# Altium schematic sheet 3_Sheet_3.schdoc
size 830 x 271 mm; Name: A_Customize; Symbol: A_Customize; Device: A_Customize; @Project Name: MyOwnMP3_PCB; REV: 1.0; Date: 2026-02-28; Sheet: 1/1; Draw By: maxyusyuk; Company: Your Company; Convert to PCB: yes; Add into BOM: yes; spicePre: .; @Page No: 3; @Page Count: 3; @Schematic Name: MyOwnMP3; @Board Name: MyOwnMP3; @Update Date: 2026-04-22; @Create Time: 17:19:00; @Update Time: 22:09:50; @Page Name: Sheet_3; @Create Date: 2026-03-28
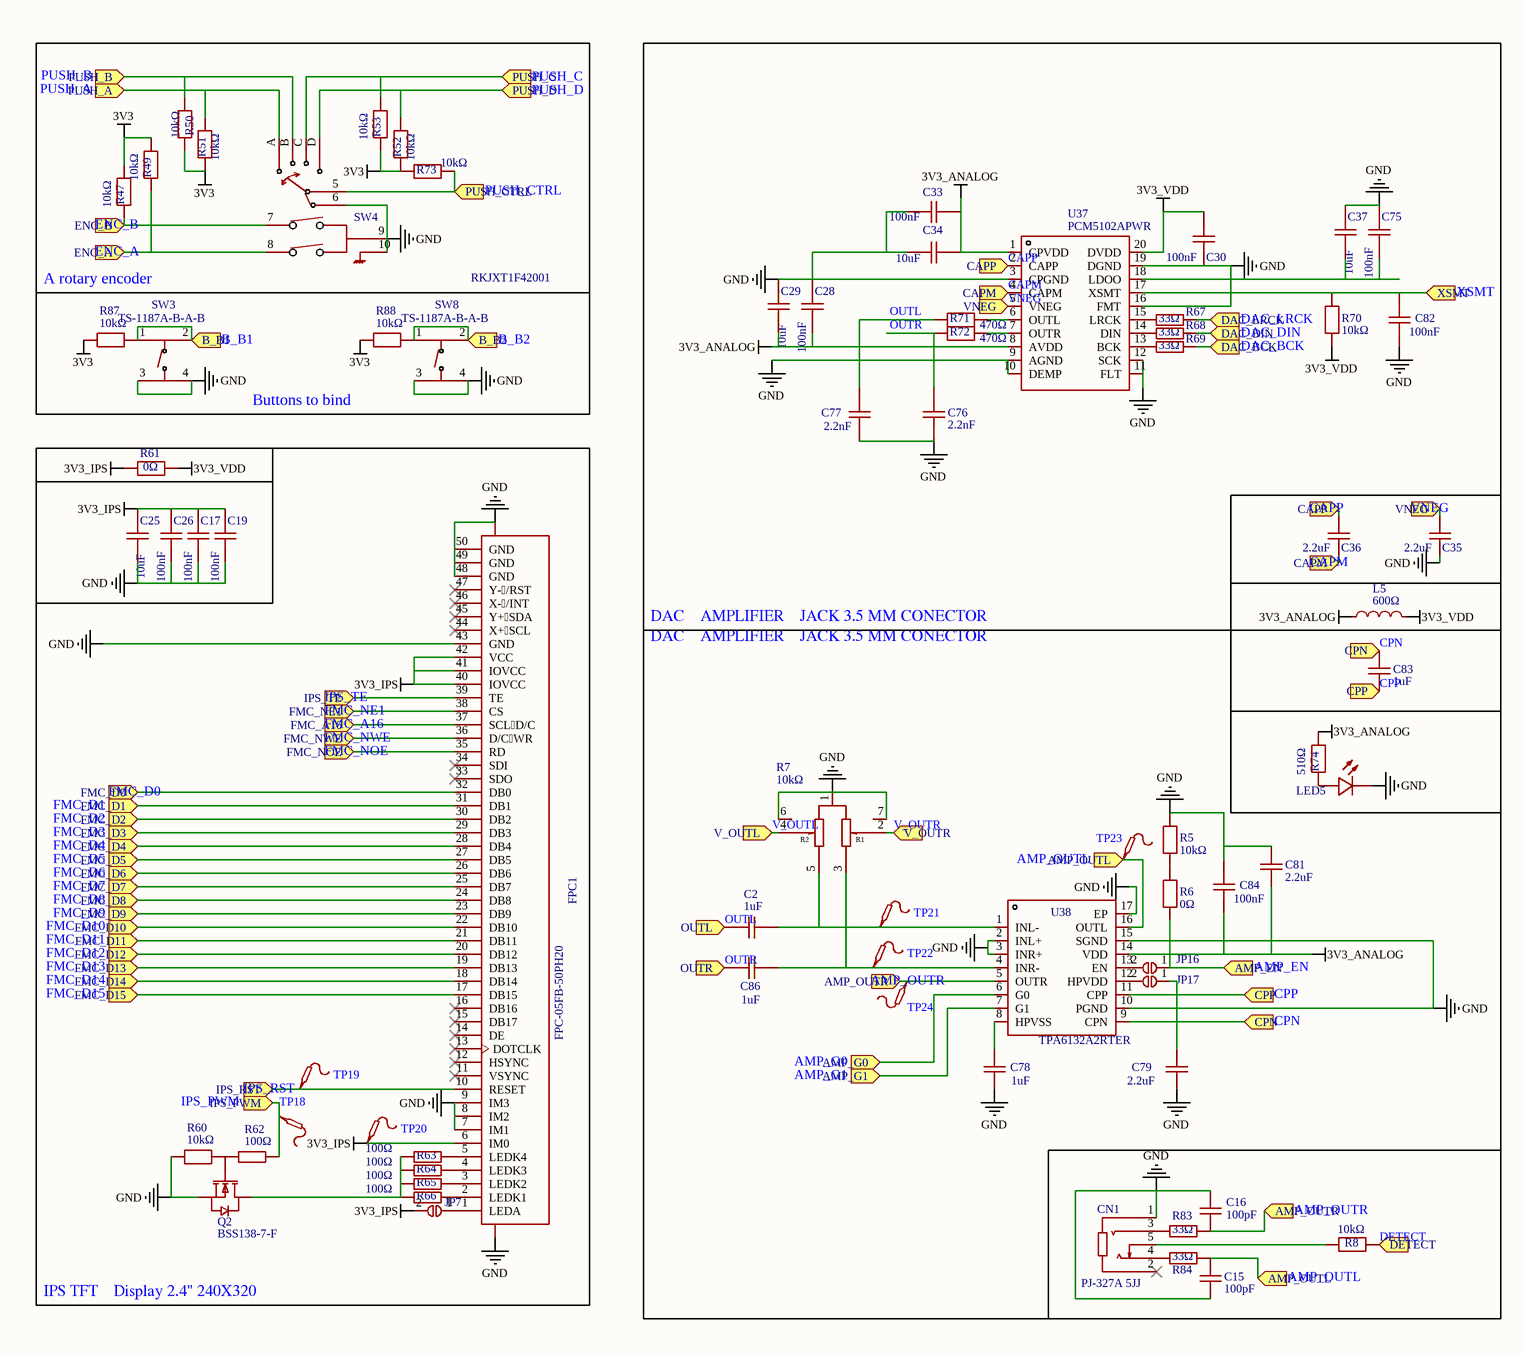
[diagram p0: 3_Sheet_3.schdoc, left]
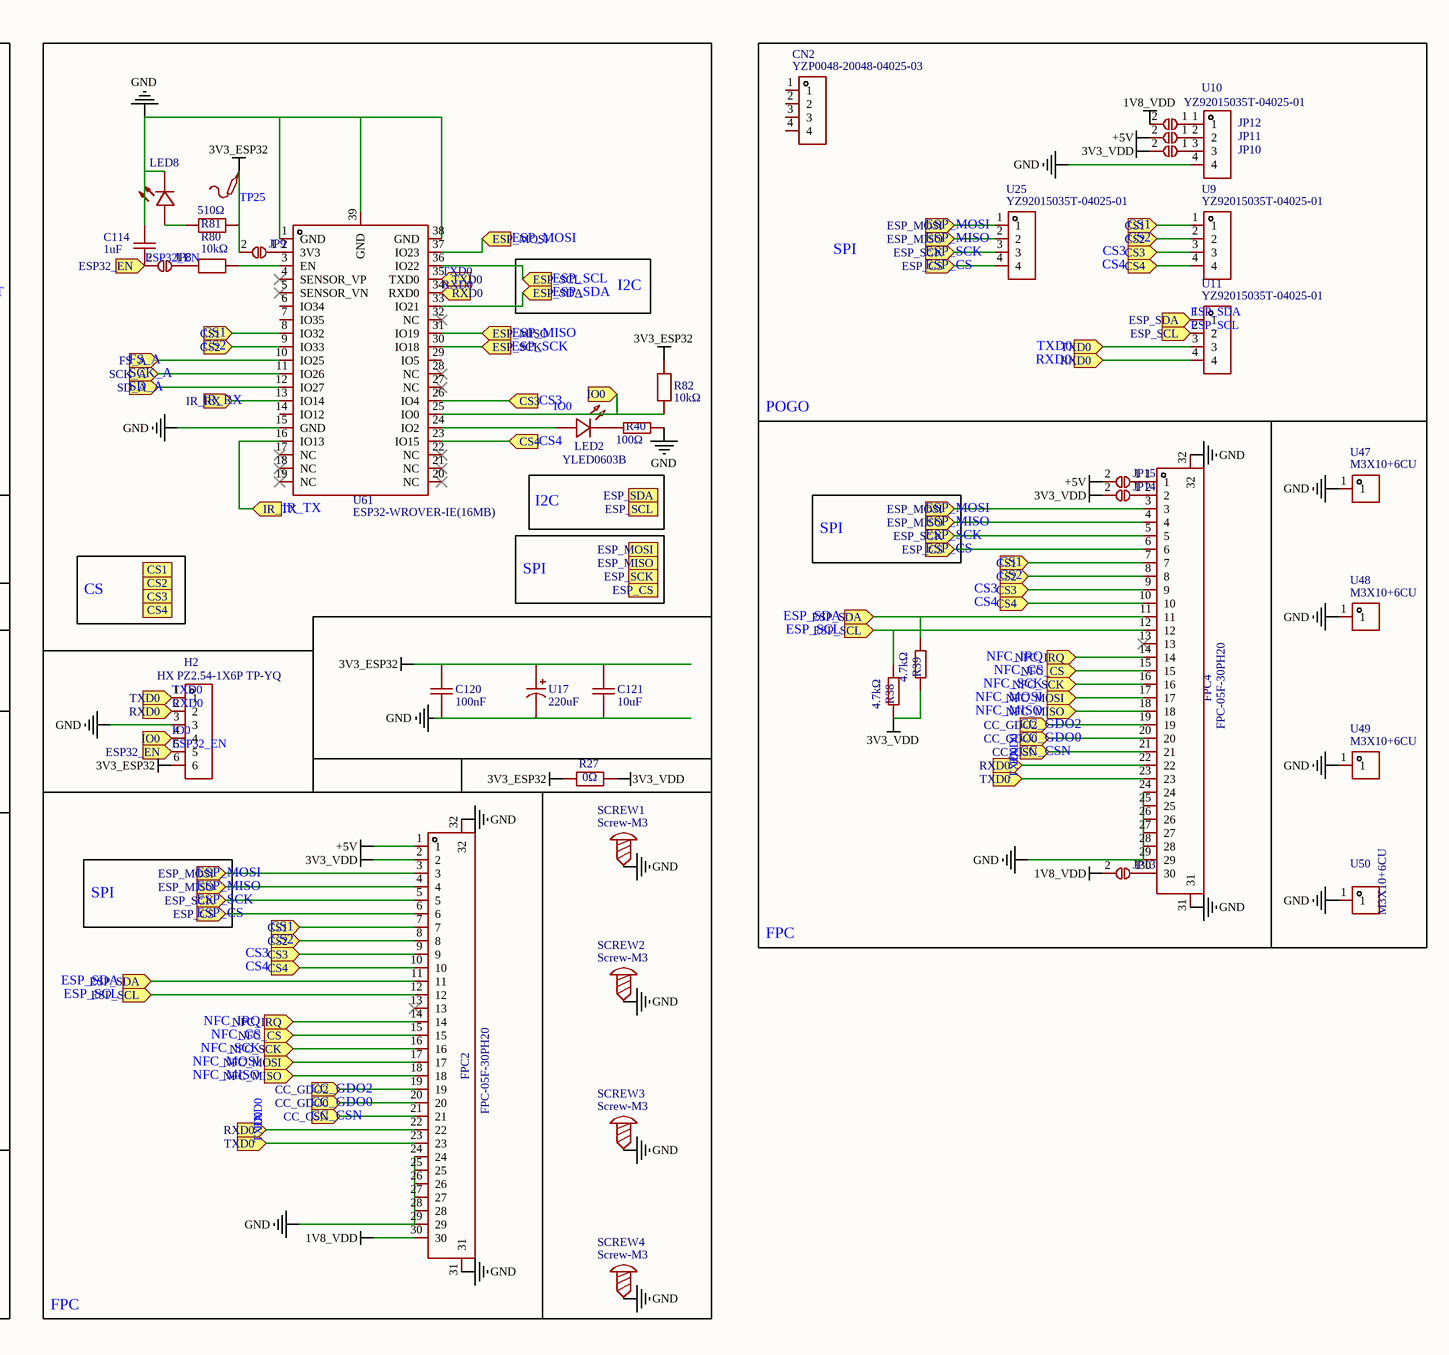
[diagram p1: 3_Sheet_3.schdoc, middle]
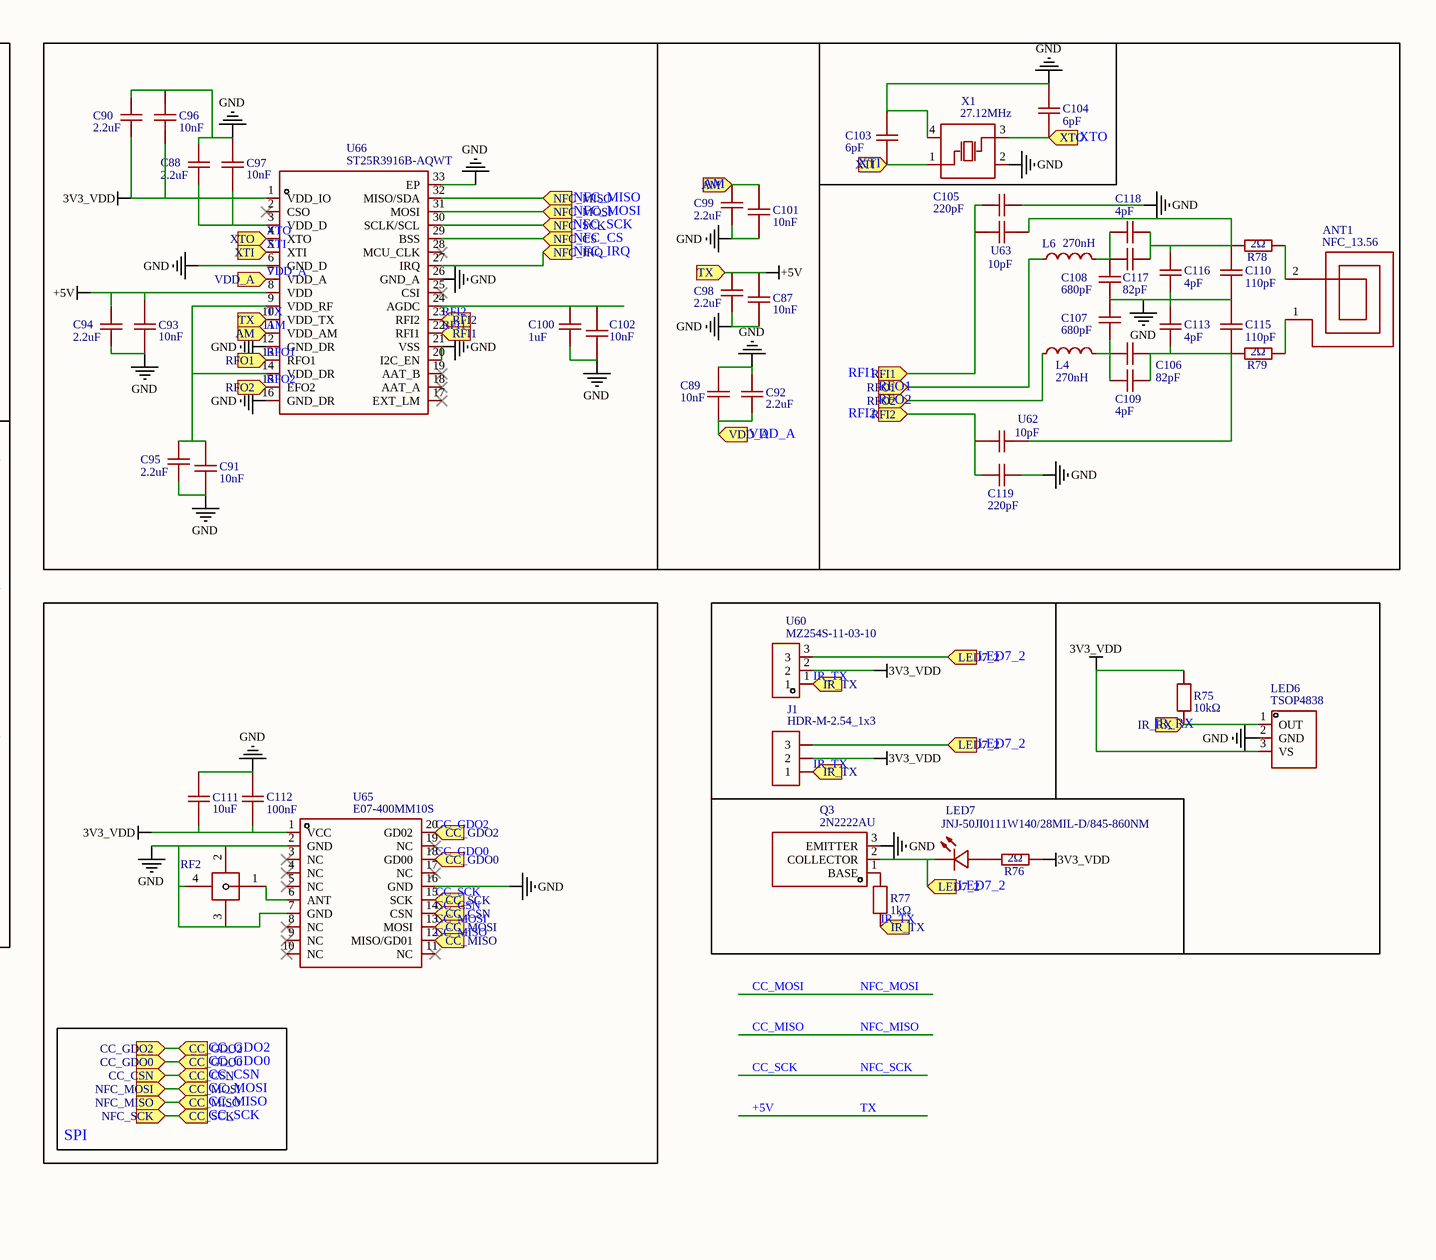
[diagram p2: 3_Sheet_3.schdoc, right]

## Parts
ANT1  NFC_13.56  [NFC ANTENNA]
C2  1uF  [C0603]
C15  100pF  [C0603]
C16  100pF  [C0603]
C17  100nF  [C0603]
C19  100nF  [C0603]
C25  10uF  [C1206]
C26  100nF  [C0603]
C28  100nF  [C0603]
C29  10uF  [C1206]
C30  100nF  [C0603]
C33  100nF  [C0603]
C34  10uF  [C1206]
C35  2.2uF  [C0603]
C36  2.2uF  [C0603]
C37  10uF  [C1206]
C75  100nF  [C0603]
C76  2.2nF  [C0805]
C77  2.2nF  [C0805]
C78  1uF  [C0603]
C79  2.2uF  [C0603]
C81  2.2uF  [C0603]
C82  100nF  [C0603]
C83  1uF  [C0603]
C84  100nF  [C0603]
C86  1uF  [C0603]
C87  10nF  [C0603]
C88  2.2uF  [C0603]
C89  10nF  [C0603]
C90  2.2uF  [C0603]
C91  10nF  [C0603]
C92  2.2uF  [C0603]
C93  10nF  [C0603]
C94  2.2uF  [C0603]
C95  2.2uF  [C0603]
C96  10nF  [C0603]
C97  10nF  [C0603]
C98  2.2uF  [C0603]
C99  2.2uF  [C0603]
C100  1uF  [C0603]
C101  10nF  [C0603]
C102  10nF  [C0603]
C103  6pF  [C0603]
C104  6pF  [C0603]
C105  220pF  [C0402]
C106  82pF  [C0603]
C107  680pF  [C0603]
C108  680pF  [C0603]
C109  4pF  [C0402]
C110  110pF  [C0402]
C111  10uF  [C1206]
C112  100nF  [C0603]
C113  4pF  [C0402]
C114  1uF  [C0603]
C115  110pF  [C0402]
C116  4pF  [C0402]
C117  82pF  [C0603]
C118  4pF  [C0402]
C119  220pF  [C0402]
C120  100nF  [C0603]
C121  10uF  [C1206]
CN1  PJ-327A 5JJ  [AUDIO-SMD_PJ-327A5JJ]
CN2  YZP0048-20048-04025-03
FPC1  FPC-05FB-50PH20  [FPC-SMD_50P-P0.50_FPC-05FB-50PH20]
FPC2  FPC-05F-30PH20  [FPC-SMD_30P-P0.50_XUNPU_FPC-05F-30PH20]
FPC4  FPC-05F-30PH20  [FPC-SMD_30P-P0.50_XUNPU_FPC-05F-30PH20]
H2  HX PZ2.54-1X6P TP-YQ  [HDR-SMD_6P-HX-PZ2.54-1X6P-TP-YQ]
J1  HDR-M-2.54_1x3  [HDR-M-2.54_1X3]
JP7  2P Solder UNBridge Jumper  [SOLDER BRIDGE 2P UNBRIDGED]  (value not drawn)
JP8  2P Solder UNBridge Jumper  [SOLDER BRIDGE 2P UNBRIDGED]  (value not drawn)
JP9  2P Solder UNBridge Jumper  [SOLDER BRIDGE 2P UNBRIDGED]  (value not drawn)
JP10  2P Solder UNBridge Jumper  [SOLDER BRIDGE 2P UNBRIDGED]  (value not drawn)
JP11  2P Solder UNBridge Jumper  [SOLDER BRIDGE 2P UNBRIDGED]  (value not drawn)
JP12  2P Solder UNBridge Jumper  [SOLDER BRIDGE 2P UNBRIDGED]  (value not drawn)
JP13  2P Solder UNBridge Jumper  [SOLDER BRIDGE 2P UNBRIDGED]  (value not drawn)
JP14  2P Solder UNBridge Jumper  [SOLDER BRIDGE 2P UNBRIDGED]  (value not drawn)
JP15  2P Solder UNBridge Jumper  [SOLDER BRIDGE 2P UNBRIDGED]  (value not drawn)
JP16  2P Solder UNBridge Jumper  [SOLDER BRIDGE 2P UNBRIDGED]  (value not drawn)
JP17  2P Solder UNBridge Jumper  [SOLDER BRIDGE 2P UNBRIDGED]  (value not drawn)
L4  270nH  [L0603]
L5  600Ω  [L0805]
L6  270nH  [L0603]
LED2  YLED0603B  [LED0603-FD]
LED5  YLED0603R  [LED0603-FD]  (value not drawn)
LED6  TSOP4838  [SENSOR-TH_TSOP4X]
LED7  JNJ-50JI0111W140/28MIL-D/845-860NM  [LED-SMD_L5.0-W5.0-LS5.3_C9900102386]
LED8  YLED0603R  [LED0603-FD]  (value not drawn)
Q2  BSS138-7-F  [SOT-23-3_L2.9-W1.6-P1.90-LS2.8-BR]
Q3  2N2222AU  [SOT-89-3_L4.5-W2.4-P1.50-LS4.0-BR]
R5  10kΩ  [R0603]
R6  0Ω  [R1206]
R7  10kΩ  [RES-SMD_RK10J12R0A0B]
R8  10kΩ  [R0603]
R27  0Ω  [R1206]
R38  4.7kΩ  [R0603]
R39  4.7kΩ  [R0603]
R40  100Ω  [R0603]
R47  10kΩ  [R0603]
R49  10kΩ  [R0603]
R50  10kΩ  [R0603]
R51  10kΩ  [R0603]
R52  10kΩ  [R0603]
R53  10kΩ  [R0603]
R60  10kΩ  [R0603]
R61  0Ω  [R1206]
R62  100Ω  [R0603]
R63  100Ω  [R0603]
R64  100Ω  [R0603]
R65  100Ω  [R0603]
R66  100Ω  [R0603]
R67  33Ω  [R0603]
R68  33Ω  [R0603]
R69  33Ω  [R0603]
R70  10kΩ  [R0603]
R71  470Ω  [R0603]
R72  470Ω  [R0603]
R73  10kΩ  [R0603]
R74  510Ω  [R0603]
R75  10kΩ  [R0603]
R76  2Ω  [R2512]
R77  1kΩ  [R2512]
R78  2Ω  [R2512]
R79  2Ω  [R2512]
R80  10kΩ  [R0603]
R81  510Ω  [R0603]
R82  10kΩ  [R0603]
R83  33Ω  [R0603]
R84  33Ω  [R0603]
R87  10kΩ  [R0603]
R88  10kΩ  [R0603]
RF2  HC-RF-IPEX0303-01  [IPEX-SMD_HC-RF-IPEX0303-01]  (value not drawn)
SCREW1  Screw-M3  [SCREW-M3]
SCREW2  Screw-M3  [SCREW-M3]
SCREW3  Screw-M3  [SCREW-M3]
SCREW4  Screw-M3  [SCREW-M3]
SW3  TS-1187A-B-A-B  [SW-SMD_4P-L5.1-W5.1-P3.70-LS6.5-TL_H1.5]
SW4  RKJXT1F42001  [SW-TH_RKJXT1F42001]
SW8  TS-1187A-B-A-B  [SW-SMD_4P-L5.1-W5.1-P3.70-LS6.5-TL_H1.5]
TP18  (no value)  [Test-Point-0.5mm]
TP19  (no value)  [Test-Point-0.5mm]
TP20  (no value)  [Test-Point-0.5mm]
TP21  (no value)  [Test-Point-0.5mm]
TP22  (no value)  [Test-Point-0.5mm]
TP23  (no value)  [Test-Point-0.5mm]
TP24  (no value)  [Test-Point-0.5mm]
TP25  (no value)  [Test-Point-0.5mm]
U9  YZ92015035T-04025-01  [CONN-SMD_4P-P2.50_YZ92015035T-04025-01]
U10  YZ92015035T-04025-01  [CONN-SMD_4P-P2.50_YZ92015035T-04025-01]
U11  YZ92015035T-04025-01  [CONN-SMD_4P-P2.50_YZ92015035T-04025-01]
U17  220uF  [CAP-SMD_BD6.3-L6.5-W6.5-LS7.2-FD]
U25  YZ92015035T-04025-01  [CONN-SMD_4P-P2.50_YZ92015035T-04025-01]
U37  PCM5102APWR  [TSSOP-20_L6.5-W4.4-P0.65-LS6.4-BL]
U38  TPA6132A2RTER  [WQFN-16_L3.0-W3.0-P0.50-TL-EP1.6]
U47  M3X10+6CU  [SMD_L4.7-W4.7-D3.0]
U48  M3X10+6CU  [SMD_L4.7-W4.7-D3.0]
U49  M3X10+6CU  [SMD_L4.7-W4.7-D3.0]
U50  M3X10+6CU  [SMD_L4.7-W4.7-D3.0]
U60  MZ254S-11-03-10  [HDR-SMD_3P-P2.54-H-M_MZ254S-11-03-10]
U61  ESP32-WROVER-IE(16MB)  [WIFI-SMD_ESP32-WROVER-E-N8R2]
U62  10pF  [C0603]
U63  10pF  [C0603]
U65  E07-400MM10S  [COMM-SMD_E07-400MM10S]
U66  ST25R3916B-AQWT  [VFQFPN-32_L5.0-W5.0-P0.50-TL-EP3.5]
X1  27.12MHz  [CRYSTAL-SMD_4P-L3.2-W2.5-BL]

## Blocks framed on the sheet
IPS TFT  Display 2.4" 240X320: C17 C19 C25 C26 FPC1 JP7 Q2 R60-R66 TP18-TP20
SPI: C111 C112 RF2 U65

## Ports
AM (in), AMP_EN (in), AMP_G0 (in), AMP_G1 (in), AMP_OUTL (in), AMP_OUTR (in), B_B1 (in), B_B2 (in), CAPM (in), CAPP (in), CC_CSN (in), CC_GDO0 (in), CC_GDO2 (in), CC_MISO (in), CC_MOSI (in), CC_SCK (in), CPN (in), CPP (in), CS1 (in), CS2 (in), CS3 (in), CS4 (in), DAC_BCK (in), DAC_DIN (in), DAC_LRCK (in), DETECT (in), ENC_A (in), ENC_B (in), ESP32_EN (in), ESP_CS (in), ESP_MISO (in), ESP_MOSI (in), ESP_SCK (in), ESP_SCL (in), ESP_SDA (in), FMC_A16 (in), FMC_D0 (in), FMC_D1 (in), FMC_D2 (in), FMC_D3 (in), FMC_D4 (in), FMC_D5 (in), FMC_D6 (in), FMC_D7 (in), FMC_D8 (in), FMC_D9 (in), FMC_D10 (in), FMC_D11 (in), FMC_D12 (in), FMC_D13 (in), FMC_D14 (in), FMC_D15 (in), FMC_NE1 (in), FMC_NOE (in), FMC_NWE (in), FS_A (in), IO0 (in), IPS_PWM (in), IPS_RST (in), IPS_TE (in), IR_RX (in), IR_TX (in), LED7_2 (in), NFC_CS (in), NFC_IRQ (in), NFC_MISO (in), NFC_MOSI (in), NFC_SCK (in), OUTL (in), OUTR (in), PUSH_A (in), PUSH_B (in), PUSH_C (in), PUSH_CTRL (in), PUSH_D (in), RFI1 (in), RFI2 (in), RFO1 (in), RFO2 (in), RXD0 (in), SCK_A (in), SD_A (in), TX (in), TXD0 (in), V_OUTL (in), V_OUTR (in), VDD_A (in), VNEG (in), XSMT (in), XTI (in), XTO (in)

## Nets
1V8_VDD: FPC2.30 JP12.2(B) JP13.2(B)
3V3: R47.2 R49.2 R50.2 R51.2 R52.1 R53.1 R73.2 R87.2 R88.2
3V3_ANALOG: C28.2 C29.1 C33.2 C34.1 C81.2 C84.2 L5.1 R74.1 U37.1(CPVDD) U37.8(AVDD) U38.14(VDD)
3V3_ESP32: C120.2 C121.1 H2.6 JP9.2(B) R27.1 R81.1 R82.1 TP25.1 U17.1
3V3_IPS: C17.1 C19.1 C25.2 C26.1 FPC1.6(IM0) FPC1.40(IOVCC) FPC1.41(IOVCC) FPC1.42(VCC) JP7.2(B) R61.1 TP20.1
3V3_VDD: C30.1 C90.1 C96.1 C111.2 C112.1 FPC2.2 J1.2 JP10.2(B) JP14.2(B) L5.2 LED6.3(VS) R27.2 R38.1 R39.1 R61.2 R70.2 R75.1 R76.2 U37.20(DVDD) U60.2 U65.1(VCC) U66.1(VDD_IO)
+5V: C87.2 C93.2 C94.2 C98.2 FPC2.1 JP11.2(B) JP15.2(B) U66.8(VDD) U66.10(VDD_TX) ; port TX  [also labelled TX]
GND: C15.1 C16.2 C17.2 C19.2 C25.1 C26.2 C28.1 C29.2 C30.2 C33.1 C34.2 C35.2 C37.2 C75.1 C76.1 C77.1 C78.1 C79.1 C81.1 C82.2 C84.1 C87.1 C88.2 C89.2 C90.2 C91.1 C92.1 C93.1 C94.1 C95.1 C96.2 C97.2 C98.1 C99.1 C100.2 C101.1 C102.1 C103.1 C104.1 C105.2 C107.2 C108.1 C110.1 C111.1 C112.2 C113.2 C114.1 C115.2 C116.1 C119.2 C120.1 C121.2 CN1.1 FPC1.7(IM1) FPC1.8(IM2) FPC1.9(IM3) FPC1.43(GND) FPC1.48(GND) FPC1.49(GND) FPC1.50(GND) FPC1.51(PAD1) FPC1.52(PAD2) FPC2.24 FPC2.25 FPC2.26 FPC2.27 FPC2.28 FPC2.29 FPC2.31 FPC2.32 FPC4.24 FPC4.25 FPC4.26 FPC4.27 FPC4.28 FPC4.29 FPC4.31 FPC4.32 H2.3 LED5.2(-) LED6.2(GND) LED8.2(-) Q2.2(S) Q3.3(EMITTER) R5.2 R7.1 R7.6(EH) R7.7(EH) R40.2 R60.2 RF2.2 RF2.3 RF2.4 SCREW1.1 SCREW2.1 SCREW3.1 SCREW4.1 SW3.3(C) SW3.4(D) SW4.6(COM) SW4.9(E_C) SW4.10 SW8.3(C) SW8.4(D) U10.4 U17.2 U37.3(CPGND) U37.9(AGND) U37.10(DEMP) U37.11(FLT) U37.12(SCK) U37.16(FMT) U37.19(DGND) U38.2(INL+) U38.3(INR+) U38.10(PGND) U38.15(SGND) U38.17(EP) U47.1 U48.1 U49.1 U50.1 U61.1(GND) U61.15(GND) U61.38(GND) U61.39(GND) U65.2(GND) U65.7(GND) U65.16(GND) U66.6(GND_D) U66.12(GND_DR) U66.16(GND_DR) U66.20(I2C_EN) U66.21(VSS) U66.26(GND_A) U66.33(EP) X1.2(GND) X1.4(GND)
AM: C99.2 C101.2 U66.11(VDD_AM) ; port AM
AMP_EN: JP16.1(A) R6.2 ; port AMP_EN
AMP_G0: U38.6(G0) ; port AMP_G0
AMP_G1: U38.7(G1) ; port AMP_G1
AMP_OUTL: C15.2 R84.2 TP23.1 U38.16(OUTL) ; port AMP_OUTL
AMP_OUTR: C16.1 R83.2 TP24.1 U38.5(OUTR) ; port AMP_OUTR
B_B1: R87.1 SW3.1(A) SW3.2(B) ; port B_B1
B_B2: R88.1 SW8.1(A) SW8.2(B) ; port B_B2
CAPM: C36.2 U37.4(CAPM) ; port CAPM
CAPP: C36.1 U37.2(CAPP) ; port CAPP
CC_CSN: FPC2.21 FPC4.21 U65.14(CSN) ; port CC_CSN
CC_GDO0: FPC2.20 FPC4.20 U65.18(GD00) ; port CC_GDO0
CC_GDO2: FPC2.19 FPC4.19 U65.20(GD02) ; port CC_GDO2
CC_MISO: FPC2.18 FPC4.18 U65.12(MISO/GD01) U66.32(MISO/SDA) ; port CC_MISO, port NFC_MISO  [also labelled NFC_MISO]
CC_MOSI: FPC2.17 FPC4.17 U65.13(MOSI) U66.31(MOSI) ; port CC_MOSI, port NFC_MOSI  [also labelled NFC_MOSI]
CC_SCK: FPC2.16 FPC4.16 U65.15(SCK) U66.30(SCLK/SCL) ; port CC_SCK, port NFC_SCK  [also labelled NFC_SCK]
CPN: C83.1 U38.9(CPN) ; port CPN
CPP: C83.2 U38.11(CPP) ; port CPP
CS1: FPC2.7 FPC4.7 U9.1 U61.8(IO32) ; port CS1
CS2: FPC2.8 FPC4.8 U9.2 U61.9(IO33) ; port CS2
CS3: FPC2.9 FPC4.9 U9.3 U61.26(IO4) ; port CS3
CS4: FPC2.10 FPC4.10 U9.4 U61.23(IO15) ; port CS4
DAC_BCK: R69.2 ; port DAC_BCK
DAC_DIN: R68.2 ; port DAC_DIN
DAC_LRCK: R67.2 ; port DAC_LRCK
DETECT: R8.1 ; port DETECT
ENC_A: R49.1 SW4.8(E_A) ; port ENC_A
ENC_B: R47.1 SW4.7(E_B) ; port ENC_B
ESP32_EN: C114.2 H2.5 JP8.2(B) ; port ESP32_EN
ESP_CS: FPC2.6 FPC4.6 U25.4 ; port ESP_CS
ESP_MISO: FPC2.4 FPC4.4 U25.2 U61.31(IO19) ; port ESP_MISO
ESP_MOSI: FPC2.3 FPC4.3 U25.1 U61.37(IO23) ; port ESP_MOSI
ESP_SCK: FPC2.5 FPC4.5 U25.3 U61.30(IO18) ; port ESP_SCK
ESP_SCL: FPC2.12 FPC4.12 R38.2 U11.2 U61.36(IO22) ; port ESP_SCL
ESP_SDA: FPC2.11 FPC4.11 R39.2 U11.1 U61.33(IO21) ; port ESP_SDA
FMC_A16: FPC1.37(SCL D/C) ; port FMC_A16
FMC_D0: FPC1.32(DB0) ; port FMC_D0
FMC_D1: FPC1.31(DB1) ; port FMC_D1
FMC_D2: FPC1.30(DB2) ; port FMC_D2
FMC_D3: FPC1.29(DB3) ; port FMC_D3
FMC_D4: FPC1.28(DB4) ; port FMC_D4
FMC_D5: FPC1.27(DB5) ; port FMC_D5
FMC_D6: FPC1.26(DB6) ; port FMC_D6
FMC_D7: FPC1.25(DB7) ; port FMC_D7
FMC_D8: FPC1.24(DB8) ; port FMC_D8
FMC_D9: FPC1.23(DB9) ; port FMC_D9
FMC_D10: FPC1.22(DB10) ; port FMC_D10
FMC_D11: FPC1.21(DB11) ; port FMC_D11
FMC_D12: FPC1.20(DB12) ; port FMC_D12
FMC_D13: FPC1.19(DB13) ; port FMC_D13
FMC_D14: FPC1.18(DB14) ; port FMC_D14
FMC_D15: FPC1.17(DB15) ; port FMC_D15
FMC_NE1: FPC1.38(CS) ; port FMC_NE1
FMC_NOE: FPC1.35(RD) ; port FMC_NOE
FMC_NWE: FPC1.36(D/C WR) ; port FMC_NWE
FS_A: U61.10(IO25) ; port FS_A
IO0: H2.4 R82.2 U61.25(IO0) ; port IO0
IPS_PWM: R62.2 TP18.1 ; port IPS_PWM
IPS_RST: FPC1.10(RESET) TP19.1 ; port IPS_RST
IPS_TE: FPC1.39(TE) ; port IPS_TE
IR_RX: LED6.1(OUT) R75.2 U61.13(IO14) ; port IR_RX
IR_TX: J1.1 R77.1 U60.1 U61.16(IO13) ; port IR_TX
LED7_2: J1.3 LED7.2(K) Q3.2(COLLECTOR) U60.3 ; port LED7_2
NFC_CS: FPC2.15 FPC4.15 U66.29(BSS) ; port NFC_CS
NFC_IRQ: FPC2.14 FPC4.14 U66.27(IRQ) ; port NFC_IRQ
OUTL: C2.2 ; port OUTL
OUTR: C86.2 ; port OUTR
PUSH_A: R51.1 SW4.A ; port PUSH_A
PUSH_B: R50.1 SW4.B ; port PUSH_B
PUSH_C: R53.2 SW4.C ; port PUSH_C
PUSH_CTRL: R73.1 SW4.5(PUSH) ; port PUSH_CTRL
PUSH_D: R52.2 SW4.D ; port PUSH_D
RFI1: C105.1 U63.1 U66.22(RFI1) ; port RFI1
RFI2: C119.1 U62.1 U66.23(RFI2) ; port RFI2
RFO1: L6.1 U66.13(RFO1) ; port RFO1
RFO2: L4.1 U66.15(EFO2) ; port RFO2
RXD0: FPC2.22 FPC4.22 H2.2 U11.4 U61.34(RXD0) ; port RXD0
SCK_A: U61.11(IO26) ; port SCK_A
SD_A: U61.12(IO27) ; port SD_A
TXD0: FPC2.23 FPC4.23 H2.1 U11.3 U61.35(TXD0) ; port TXD0
V_OUTL: R7.4 ; port V_OUTL
V_OUTR: R7.2 ; port V_OUTR
VDD_A: C89.1 C92.2 U66.7(VDD_A) ; port VDD_A
VNEG: C35.1 U37.5(VNEG) ; port VNEG
XSMT: C82.1 R70.1 U37.17(XSMT) ; port XSMT
XTI: C103.2 U66.5(XTI) X1.1(OSC1) ; port XTI
XTO: C104.2 U66.4(XTO) X1.3(OSC2) ; port XTO
NetANT1_1: ANT1.1 R79.2
NetANT1_2: ANT1.2 R78.2
NetC2_1: C2.1 R7.5 TP21.1 U38.1(INL-)
NetC37_1: C37.1 C75.2 U37.18(LDOO)
NetC76_2: C76.2 R72.1
NetC77_2: C77.2 R71.1
NetC78_2: C78.2 U38.8(HPVSS)
NetC79_2: C79.2 JP17.1(A)
NetC86_1: C86.1 R7.3 TP22.1 U38.4(INR-)
NetC88_1: C88.1 C97.1 U66.3(VDD_D)
NetC91_2: C91.2 C95.2 U66.9(VDD_RF) U66.14(VDD_DR)
NetC100_1: C100.1 C102.2 U66.24(AGDC)
NetC106_1: C106.1 C107.1 C109.2 L4.2
NetC106_2: C106.2 C109.1 C113.1 C115.1 R79.1 U62.2
NetC108_2: C108.2 C117.1 C118.2 L6.2
NetC110_2: C110.2 C116.2 C117.2 C118.1 R78.1 U63.2
NetCN1_3: CN1.3 R83.1
NetCN1_4: CN1.4 R84.1
NetCN1_5: CN1.5 R8.2
NetFPC1_1: FPC1.1(LEDA) JP7.1(A)
NetFPC1_2: FPC1.2(LEDK1) R66.2
NetFPC1_3: FPC1.3(LEDK2) R65.2
NetFPC1_4: FPC1.4(LEDK3) R64.2
NetFPC1_5: FPC1.5(LEDK4) R63.2
NetFPC4_1: FPC4.1 JP15.1(A)
NetFPC4_2: FPC4.2 JP14.1(A)
NetFPC4_30: FPC4.30 JP13.1(A)
NetJP8_1: JP8.1(A) R80.1
NetJP9_1: JP9.1(A) U61.2(3V3)
NetJP10_1: JP10.1(A) U10.3
NetJP11_1: JP11.1(A) U10.2
NetJP12_1: JP12.1(A) U10.1
NetJP16_2: JP16.2(B) U38.13(EN)
NetJP17_2: JP17.2(B) U38.12(HPVDD)
NetLED2_1: LED2.1(A) U61.24(IO2)
NetLED2_2: LED2.2(K) R40.1
NetLED5_1: LED5.1(+) R74.2
NetLED7_1: LED7.1(A) R76.1
NetLED8_1: LED8.1(+) R81.2
NetQ2_1: Q2.1(G) R60.1 R62.1
NetQ2_3: Q2.3(D) R63.1 R64.1 R65.1 R66.1
NetQ3_1: Q3.1(BASE) R77.2
NetR5_1: R5.1 R6.1
NetR67_1: R67.1 U37.15(LRCK)
NetR68_1: R68.1 U37.14(DIN)
NetR69_1: R69.1 U37.13(BCK)
NetR71_2: R71.2 U37.6(OUTL)
NetR72_2: R72.2 U37.7(OUTR)
NetR80_2: R80.2 U61.3(EN)
NetRF2_1: RF2.1 U65.6(ANT)

Not connected (* = marked no-connect by the designer): CN1 2*; CN2 1 2 3 4; FPC1 11(VSYNC)* 12(HSYNC)* 13(DOTCLK)* 14(DE)* 15(DB17)* 16(DB16)* 33(SDO)* 34(SDI)* 44(X+ SCL)* 45(Y+ SDA)* 46(X- /INT)* 47(Y- /RST)*; FPC2 13*; FPC4 13*; U61 4(SENSOR_VP)* 5(SENSOR_VN)* 6(IO34) 7(IO35) 14(IO12) 17(NC)* 18(NC)* 19(NC)* 20(NC)* 21(NC)* 22(NC)* 27(NC)* 28(NC)* 29(IO5) 32(NC)*; U65 3(NC)* 4(NC)* 5(NC)* 8(NC)* 9(NC)* 10(NC)* 11(NC)* 17(NC)* 19(NC)*; U66 2(CSO)* 17(EXT_LM)* 18(AAT_A)* 19(AAT_B)* 25(CSI)* 28(MCU_CLK)*

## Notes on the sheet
- A rotary encoder
- I2C
- SPI
- Buttons to bind
- POGO
- DAC  AMPLIFIER  JACK 3.5 MM CONECTOR
- CS
- FPC
- Labels drawn without touching a wire or pin: AM, AMP_EN, AMP_G0, AMP_G1, AMP_OUTL, AMP_OUTR, B_B1, B_B2, CAPM, CAPP, CC_CSN, CC_GDO0, CC_GDO2, CC_MISO, CC_MOSI, CC_SCK, CPN, CPP, CS1, CS2, CS3, CS4, DAC_BCK, DAC_DIN, DAC_LRCK, ENC_A, ENC_B, ESP_CS, ESP_MISO, ESP_MOSI, ESP_SCK, ESP_SCL, ESP_SDA, FMC_A16, FMC_D0, FMC_D1, FMC_D2, FMC_D3, FMC_D4, FMC_D5, FMC_D6, FMC_D7, FMC_D8, FMC_D9, FMC_D10, FMC_D11, FMC_D12, FMC_D13, FMC_D14, FMC_D15, FMC_NE1, FMC_NOE, FMC_NWE, FS_A, IPS_PWM, IPS_RST, IPS_TE, IR_RX, IR_TX, LED7_2, NFC_CS, NFC_IRQ, NFC_MISO, NFC_MOSI, NFC_SCK, OUTL, OUTR, PUSH_A, PUSH_B, PUSH_C, PUSH_CTRL, PUSH_D, RFI1, RFI2, RFO1, RFO2, RXD0, SCK_A, SD_A, TXD0, VDD_A, VNEG, XSMT, XTI, XTO

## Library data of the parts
ANT1 = NFC_13.56: Convert to PCB: yes; Add into BOM: no; Contributor: diegozalez
C2 C86 = 1uF: Manufacturer: SAMSUNG(三星); Manufacturer Part: CL10B105KB8NQNC; Convert to PCB: yes; Contributor: lcsc; nameAlias: Value
C15 C16 = 100pF: Manufacturer Part: CL10C101JB8NNNC; Manufacturer: SAMSUNG(三星); Convert to PCB: yes; nameAlias: Value
C17 C19 C26 C28 C30 C33 C75 C82 C84 C112 C120 = 100nF: Manufacturer: YAGEO(国巨); Manufacturer Part: CC0603JRX7R8BB104; Convert to PCB: yes; nameAlias: Value; Contributor: LCSC
C25 C29 C34 C37 C111 C121 = 10uF: Manufacturer: CCTC(三环); Manufacturer Part: TCC1206X7R106K160HT; Convert to PCB: yes; nameAlias: Value; Contributor: LCSC
C35 C36 C79 C81 C88 C90 C92 C94 C95 C98 C99 = 2.2uF: Manufacturer: YAGEO(国巨); Manufacturer Part: CC0603KRX5R7BB225; Convert to PCB: yes; nameAlias: Value
C76 C77 = 2.2nF: Manufacturer: Walsin(华新科); Manufacturer Part: 0805B222K102CT; Convert to PCB: yes; nameAlias: Value; Contributor: lcsc
C78 C83 C100 C114 = 1uF: Manufacturer Part: CC0603KRX5R8BB105; Manufacturer: YAGEO(国巨); Convert to PCB: yes; nameAlias: Value
C87 C89 C91 C93 C96 C97 C101 C102 = 10nF: Manufacturer: TORCH(火炬); Manufacturer Part: CC0603X7R25V103KN; Convert to PCB: yes; Contributor: lcsc; nameAlias: Value
C103 C104 = 6pF: Manufacturer: YAGEO(国巨); Manufacturer Part: CC0603CRNPO9BN6R0; Convert to PCB: yes; nameAlias: Value; Contributor: LCSC
C105 C119 = 220pF: Manufacturer: FH(风华); Manufacturer Part: 0402CG221J500NT; Convert to PCB: yes; nameAlias: Value
C106 C117 = 82pF: Manufacturer: FH(风华); Manufacturer Part: 0603CG820J500NT; Convert to PCB: yes; nameAlias: Value
C107 C108 = 680pF: Manufacturer: FH(风华); Manufacturer Part: 0603B681K500NT; Convert to PCB: yes; nameAlias: Value
C109 C113 C116 C118 = 4pF: Manufacturer: FH(风华); Manufacturer Part: 0402CG4R0C500NT; Convert to PCB: yes; nameAlias: Value
C110 C115 = 110pF: Manufacturer: muRata(村田); Manufacturer Part: GRM1555C1H111JA01D; Convert to PCB: yes; nameAlias: Value; Contributor: lcsc
CN1 = PJ-327A 5JJ: Manufacturer: SHOU HAN(首韩); Convert to PCB: yes; Contributor: LCSC
CN2 = YZP0048-20048-04025-03: Manufacturer: Xinyangze(鑫扬泽); Convert to PCB: no; Origin Footprint: CONN-SMD_4P-P2.50-YZP0048-20048-04025-03; Contributor: lcsc
FPC1 = FPC-05FB-50PH20: Manufacturer: XUNPU(讯普); Symbol: BuyDisplay ER-TFT024IPS-3 FPC - 50pin 0.5mm; Add into BOM: yes; Locking Feature: Hinged Lid; Number of Contacts: 50P; Pitch: 0.5mm; FFC, FCB Thickness: 0.3mm; Rated Voltage (Max): 50V; Current Rating (Max): 500mA
FPC2 FPC4 = FPC-05F-30PH20: Manufacturer: XUNPU(讯普); Convert to PCB: yes; Contributor: LCSC
H2 = HX PZ2.54-1X6P TP-YQ: Manufacturer: hanxia(韩下); Convert to PCB: yes
J1 = HDR-M-2.54_1x3: Convert to PCB: yes; Add into BOM: no; Contributor: LCEDA_Lib
JP7-JP17 = 2P Solder UNBridge Jumper: Manufacturer Part: DNP; Convert to PCB: yes; Add into BOM: no; Contributor: RonNovy
L4 L6 = 270nH: Manufacturer: FH(风华); Manufacturer Part: VHF160808HR27JT; Convert to PCB: yes; Add into BOM: no; nameAlias: Value; Contributor: LCSC
L5 = 600Ω: Manufacturer: FH(风华); Manufacturer Part: CBG201209U601T; Convert to PCB: yes; nameAlias: Value
LED2 = YLED0603B: Manufacturer: YONGYUTAI(永裕泰); Convert to PCB: yes; Contributor: lcsc
LED5 LED8 = YLED0603R: Manufacturer: YONGYUTAI(永裕泰); Convert to PCB: yes; Contributor: lcsc
LED6 = TSOP4838: Manufacturer: VISHAY(威世); Convert to PCB: yes; Contributor: LCSC
LED7 = JNJ-50JI0111W140/28MIL-D/845-860NM: Manufacturer: JNJOPTO(强生光电); Convert to PCB: yes; Contributor: lcsc
Q2 = BSS138-7-F: Manufacturer: DIODES(美台); Convert to PCB: yes
Q3 = 2N2222AU: Manufacturer: CBI(创基); Convert to PCB: yes; Contributor: lcsc
R5 R8 R47 R49-R53 R60 R70 R73 R75 R80 R82 R87 R88 = 10kΩ: Manufacturer: VO(翔胜); Manufacturer Part: SCR0603J10K; Convert to PCB: yes; nameAlias: Value; Contributor: lcsc
R6 R27 R61 = 0Ω: Manufacturer: JIERR(捷而瑞); Manufacturer Part: JER1206F1R000; Convert to PCB: yes; nameAlias: Value; Contributor: lcsc
R7 = 10kΩ: Manufacturer: ALPSALPINE(阿尔卑斯阿尔派); Manufacturer Part: RK10J12R0A0B; Convert to PCB: yes; Contributor: LCSC; nameAlias: Value
R38 R39 = 4.7kΩ: Manufacturer: UNI-ROYAL(厚声); Manufacturer Part: 0603WAF4701T5E; Convert to PCB: yes; nameAlias: Value
R40 R62-R66 = 100Ω: Manufacturer: YAGEO(国巨); Manufacturer Part: AF0603FR-07100RL; Convert to PCB: yes; nameAlias: Value; Contributor: LCSC
R67-R69 R83 R84 = 33Ω: Manufacturer: LIZ(丽智电子); Manufacturer Part: CR0603JA0330G; Convert to PCB: yes; nameAlias: Value
R71 R72 = 470Ω: Manufacturer: EVER OHMS(天二科技); Manufacturer Part: CR0603J470RP05Z; Convert to PCB: yes; Contributor: LCSC; nameAlias: Value
R74 R81 = 510Ω: Manufacturer: FOJAN(富捷); Manufacturer Part: FRC0603F5100TS; Convert to PCB: yes; nameAlias: Value; Contributor: lcsc
R76 R78 R79 = 2Ω: Manufacturer: UNI-ROYAL(厚声); Manufacturer Part: 25121WF200KT4E; Convert to PCB: yes; nameAlias: Value
R77 = 1kΩ: Manufacturer: FOJAN(富捷); Manufacturer Part: FRC2512J102 TS; Convert to PCB: yes; nameAlias: Value; Contributor: lcsc
RF2 = HC-RF-IPEX0303-01: Manufacturer: HCTL(华灿天禄); Convert to PCB: yes; Contributor: LCSC
SCREW1-SCREW4 = Screw-M3: Convert to PCB: yes; Contributor: EasyEDA
SW3 SW8 = TS-1187A-B-A-B: Manufacturer: XKB Connection(中国星坤); Convert to PCB: yes; Contributor: LCSC
SW4 = RKJXT1F42001: Manufacturer: ALPSALPINE(阿尔卑斯阿尔派); Convert to PCB: yes; Contributor: LCSC
TP18-TP25 = Test-Point: Add into BOM: no; Convert to PCB: yes
U9-U11 U25 = YZ92015035T-04025-01: Manufacturer: Xinyangze(鑫扬泽); Convert to PCB: yes; Contributor: lcsc
U17 = 220uF: Manufacturer: FOSAN(富捷/富信); Manufacturer Part: FVH010ADA221M0654; Convert to PCB: yes; nameAlias: Value; Contributor: lcsc
U37 = PCM5102APWR: Manufacturer: TI(德州仪器); Convert to PCB: yes; Contributor: LCSC
U38 = TPA6132A2RTER: Manufacturer: TI(德州仪器); Convert to PCB: yes
U47-U50 = M3X10+6CU: Manufacturer: Shuntian(顺天五金); Convert to PCB: yes; Contributor: lcsc
U60 = MZ254S-11-03-10: Manufacturer: DEALON(德艺隆); Convert to PCB: yes; Contributor: lcsc
U61 = ESP32-WROVER-IE(16MB): Manufacturer: ESPRESSIF(乐鑫); Manufacturer Part: ESP32-WROVER-IE-N16R8; Convert to PCB: yes; Contributor: LCSC
U62 U63 = 10pF: Manufacturer: FH(风华); Manufacturer Part: 0603CG100C500NT; Convert to PCB: yes; nameAlias: Value; Contributor: lcsc
U65 = E07-400MM10S: Manufacturer: EBYTE(亿佰特); Convert to PCB: yes; Contributor: lcsc
U66 = ST25R3916B-AQWT: Manufacturer: ST(意法半导体); Convert to PCB: yes; Contributor: lcsc
X1 = 27.12MHz: Manufacturer: YXC(扬兴晶振); Manufacturer Part: X32252712MSB4SI; Convert to PCB: yes; nameAlias: Value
